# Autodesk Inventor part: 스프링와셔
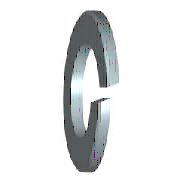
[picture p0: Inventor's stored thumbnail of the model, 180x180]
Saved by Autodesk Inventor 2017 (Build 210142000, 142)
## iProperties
Created: 2012-02
Part Number: 스프링와셔
Material: 강철, 연강
Description: 스프링 와셔
Document SubType Name: Modeling
Standard: JIS B 1251
Designer: mduedu
Standards Organization: JIS
Language: ko-KR
Size Designation: 번호 2 4
Categories: <MemberInstance><Categories><Category DisplayName="조임쇠" InternalName="e4da775c-781d-43d5-af7c-5136215cf5a6" Mnemonic="FSTN"><Category DisplayName="와셔" InternalN
Density: 7.85 g/cm^3
Appearance: 파란색 - 벽 페인트 - 광택
Mass: 0.246957 g
Surface Area: 1.02615 cm^2
Volume: 0.0314594 cm^3
IsCustomPart: 1
Author: mduedu
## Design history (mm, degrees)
sketch "스케치1"
  geometry: C1 r 3.8 at (0, 0); C2 r 2.05 at (0, 0); 1 further point
  constraints: 2 centre point, 2 coincident
  dimensions: "d0" = 4.1 diameter of C2 (= SD1); "d1" = 7.6 diameter of C1 (= SD2)
extrude "본체" new body sketch "스케치1" distance "d2" = 1 (= SD); taper "d3" = 0 deg
sketch "스케치2"
  geometry: L1 (0, -2.05)-(0, 2.05) reference; L2 (1, 3.8)-(1, -3.8) reference; L3 (-1.2, 0)-(7.2, 0) reference; L4 (0, -0.2)-(1, 0.164); L5 (0, 0.2)-(1, 0.564)
  constraints: 4 end point, 4 point on line, 1 parallel
  dimensions: "d4" = 0.2 distance from line of L3 L4.start (= 0.2 x SD); "d5" = 0.2 distance from line of L3 L5.start (= 0.2 x SD); "d6" = 70 deg angle of L2 L4 (= FAWI)
extrude "절단부" cut sketch "스케치2" stored distance "d7" = 1 (= SD); taper "d8" = 0 deg
workaxis "Work Axis1"
workplane "Work Plane1"
body "Solid1"
other parameters: "SD1" = 4.1 [user parameter; used in 1 equation term], "SD2" = 7.6 [user parameter; used in 1 equation term], "SD" = 1 [user parameter; used in 4 equation terms], "FAWI" = 70 deg [user parameter; used in 1 equation term], "d9" = 0, "d10" = 0, "d11" = 0, "d12" = 0, "SDI" = 1.4 [user parameter], "NND" = 4 [user parameter]
